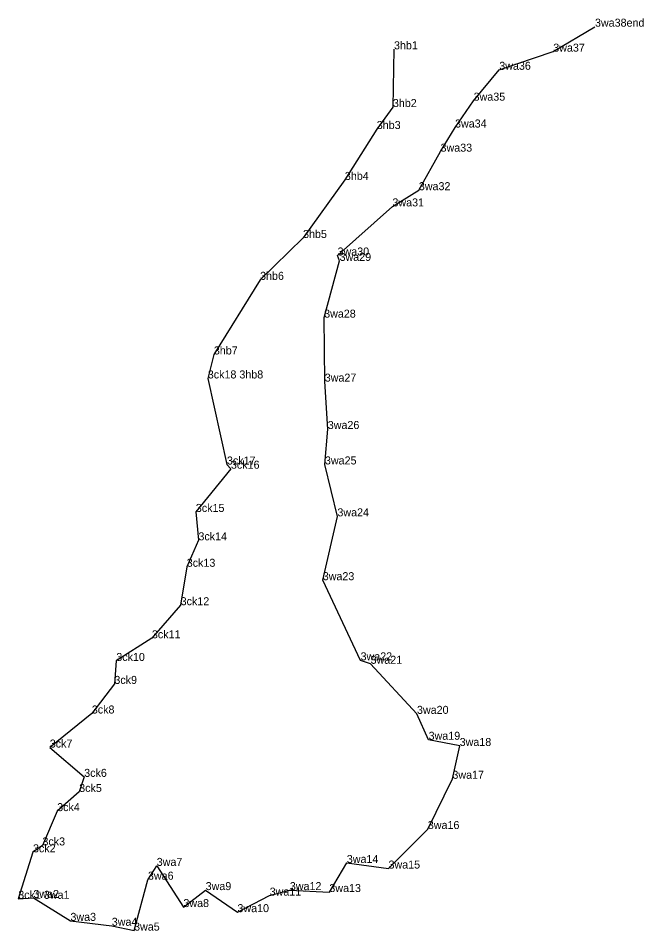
# Model space of a CAD drawing. Extents: x 2072529 to 2267990, y 436423 to 470008.
# Drawn here: x 2089643 to 2090033, y 461992 to 462561 of the extents above; entities that cross this region are included whole.
import ezdxf

# ---------------------------------------------------------------- set-up
doc = ezdxf.new("R2010")
doc.units = 0
doc.layers.add('Level 3', color=7, linetype='Continuous')
doc.layers.add('Old_Level_52', color=7, linetype='Continuous')

msp = doc.modelspace()

# ---------------------------------------------------------------- linework, layer by layer
at = {"layer": 'Level 3'}
for p, q in [((2090002.893, 462556.146), (2090002.893, 462556.146)), ((2089877.453, 462542.01), (2089877.453, 462542.01)), ((2089976.852, 462540.552), (2089976.852, 462540.552)), ((2089943.157, 462529.217), (2089943.157, 462529.217)), ((2089876.765, 462505.958), (2089876.765, 462505.958)), ((2089927.158, 462509.936), (2089927.158, 462509.936)), ((2089866.718, 462492.234), (2089866.718, 462492.234)), ((2089915.55, 462493.182), (2089915.55, 462493.182)), ((2089906.523, 462478.097), (2089906.523, 462478.097)), ((2089846.812, 462460.44), (2089846.812, 462460.44)), ((2089892.973, 462454.032), (2089892.973, 462454.032)), ((2089876.482, 462443.906), (2089876.482, 462443.906)), ((2089820.713, 462424.198), (2089820.713, 462424.198)), ((2089842.248, 462413.247), (2089842.248, 462413.247)), ((2089843.485, 462409.887), (2089843.485, 462409.887)), ((2089793.876, 462398.048), (2089793.876, 462398.048)), ((2089833.871, 462374.449), (2089833.871, 462374.449)), ((2089765.03, 462351.45), (2089765.03, 462351.45)), ((2089761.259, 462336.467), (2089761.259, 462336.467)), ((2089834.231, 462334.49), (2089834.231, 462334.49)), ((2089836.124, 462304.892), (2089836.124, 462304.892)), ((2089834.357, 462282.767), (2089834.357, 462282.767)), ((2089773.188, 462282.704), (2089773.188, 462282.704)), ((2089775.7, 462280.09), (2089775.7, 462280.09)), ((2089753.794, 462253.106), (2089753.794, 462253.106)), ((2089842.135, 462250.349), (2089842.135, 462250.349)), ((2089755.406, 462235.378), (2089755.406, 462235.378)), ((2089748.115, 462218.855), (2089748.115, 462218.855)), ((2089832.988, 462210.469), (2089832.988, 462210.469)), ((2089744.316, 462194.843), (2089744.316, 462194.843)), ((2089726.366, 462174.184), (2089726.366, 462174.184)), ((2089704.14, 462160.043), (2089704.14, 462160.043)), ((2089856.597, 462160.417), (2089856.597, 462160.417)), ((2089862.86, 462158.275), (2089862.86, 462158.275)), ((2089702.953, 462145.705), (2089702.953, 462145.705)), ((2089688.872, 462127.212), (2089688.872, 462127.212)), ((2089891.808, 462127.004), (2089891.808, 462127.004)), ((2089899.057, 462110.822), (2089899.057, 462110.822)), ((2089918.449, 462106.941), (2089918.449, 462106.941)), ((2089662.621, 462105.954), (2089662.621, 462105.954)), ((2089684.116, 462087.643), (2089684.116, 462087.643)), ((2089913.897, 462086.464), (2089913.897, 462086.464)), ((2089680.986, 462078.211), (2089680.986, 462078.211)), ((2089667.237, 462066.265), (2089667.237, 462066.265)), ((2089898.578, 462055.082), (2089898.578, 462055.082)), ((2089658.039, 462044.826), (2089658.039, 462044.826)), ((2089652.149, 462040.552), (2089652.149, 462040.552)), ((2089729.372, 462032.042), (2089729.372, 462032.042)), ((2089848.005, 462033.869), (2089848.005, 462033.869)), ((2089874.035, 462030.376), (2089874.035, 462030.376)), ((2089723.909, 462023.425), (2089723.909, 462023.425)), ((2089759.919, 462016.935), (2089759.919, 462016.935)), ((2089812.451, 462016.937), (2089812.451, 462016.937)), ((2089837.118, 462015.732), (2089837.118, 462015.732)), ((2089642.96, 462011.495), (2089642.96, 462011.495)), ((2089652.392, 462012.03), (2089652.392, 462012.03)), ((2089799.86, 462013.491), (2089799.86, 462013.491)), ((2089746.019, 462006.339), (2089746.019, 462006.339)), ((2089779.746, 462003.159), (2089779.746, 462003.159)), ((2089675.515, 461997.724), (2089675.515, 461997.724)), ((2089701.311, 461994.659), (2089701.311, 461994.659)), ((2089715.244, 461991.622), (2089715.244, 461991.622))]:
    msp.add_line(p, q, dxfattribs=at)
at = {"layer": 'Old_Level_52'}
msp.add_lwpolyline([(2089877.453, 462542.01), (2089876.765, 462505.958), (2089866.718, 462492.234), (2089846.812, 462460.44), (2089820.713, 462424.198), (2089793.876, 462398.048), (2089765.03, 462351.45), (2089761.259, 462336.467), (2089773.188, 462282.704), (2089775.7, 462280.09), (2089753.794, 462253.106), (2089755.406, 462235.378), (2089748.115, 462218.855), (2089744.316, 462194.843), (2089726.366, 462174.184), (2089704.14, 462160.043), (2089702.953, 462145.705), (2089688.872, 462127.212), (2089662.621, 462105.954), (2089684.116, 462087.643), (2089680.986, 462078.211), (2089667.237, 462066.265), (2089658.039, 462044.826), (2089652.149, 462040.552), (2089642.96, 462011.495), (2089652.392, 462012.03), (2089675.515, 461997.724), (2089701.311, 461994.659), (2089715.244, 461991.622), (2089723.909, 462023.425), (2089729.372, 462032.042), (2089746.019, 462006.339), (2089759.919, 462016.935), (2089779.746, 462003.159), (2089799.86, 462013.491), (2089812.451, 462016.937), (2089837.118, 462015.732), (2089848.005, 462033.869), (2089874.035, 462030.376), (2089898.578, 462055.082), (2089913.897, 462086.464), (2089918.449, 462106.941), (2089899.057, 462110.822), (2089891.808, 462127.004), (2089862.86, 462158.275), (2089856.597, 462160.417), (2089832.988, 462210.469), (2089842.135, 462250.349), (2089834.357, 462282.767), (2089836.124, 462304.892), (2089834.231, 462334.49), (2089833.871, 462374.449), (2089843.485, 462409.887), (2089842.248, 462413.247), (2089876.482, 462443.906), (2089892.973, 462454.032), (2089906.523, 462478.097), (2089915.55, 462493.182), (2089927.158, 462509.936), (2089943.157, 462529.217), (2089976.852, 462540.552), (2090002.893, 462556.146)], dxfattribs=at)

# ---------------------------------------------------------------- texts
for s, p in [('3wa38end', (2090002.893, 462556.146)), ('3hb1', (2089877.453, 462542.01)), ('3wa37', (2089976.852, 462540.552)), ('3wa36', (2089943.157, 462529.217)), ('3hb2', (2089876.765, 462505.958)), ('3wa35', (2089927.158, 462509.936)), ('3hb3', (2089866.718, 462492.234)), ('3wa34', (2089915.55, 462493.182)), ('3wa33', (2089906.523, 462478.097)), ('3hb4', (2089846.812, 462460.44)), ('3wa32', (2089892.973, 462454.032)), ('3wa31', (2089876.482, 462443.906)), ('3hb5', (2089820.713, 462424.198)), ('3wa30', (2089842.248, 462413.247)), ('3wa29', (2089843.485, 462409.887)), ('3hb6', (2089793.876, 462398.048)), ('3wa28', (2089833.871, 462374.449)), ('3hb7', (2089765.03, 462351.45)), ('3ck18 3hb8', (2089761.259, 462336.467)), ('3wa27', (2089834.231, 462334.49)), ('3wa26', (2089836.124, 462304.892)), ('3ck17', (2089773.188, 462282.704)), ('3ck16', (2089775.7, 462280.09)), ('3wa25', (2089834.357, 462282.767)), ('3ck15', (2089753.794, 462253.106)), ('3wa24', (2089842.135, 462250.349)), ('3ck14', (2089755.406, 462235.378)), ('3ck13', (2089748.115, 462218.855)), ('3wa23', (2089832.988, 462210.469)), ('3ck12', (2089744.316, 462194.843)), ('3ck11', (2089726.366, 462174.184)), ('3ck10', (2089704.14, 462160.043)), ('3wa22', (2089856.597, 462160.417)), ('3wa21', (2089862.86, 462158.275)), ('3ck9', (2089702.953, 462145.705)), ('3ck8', (2089688.872, 462127.212)), ('3wa20', (2089891.808, 462127.004)), ('3wa19', (2089899.057, 462110.822)), ('3wa18', (2089918.449, 462106.941)), ('3ck7', (2089662.621, 462105.954)), ('3ck6', (2089684.116, 462087.643)), ('3wa17', (2089913.897, 462086.464)), ('3ck5', (2089680.986, 462078.211)), ('3ck4', (2089667.237, 462066.265)), ('3wa16', (2089898.578, 462055.082)), ('3ck3', (2089658.039, 462044.826)), ('3ck2', (2089652.149, 462040.552)), ('3wa14', (2089848.005, 462033.869)), ('3wa7', (2089729.372, 462032.042)), ('3wa15', (2089874.035, 462030.376)), ('3wa6', (2089723.909, 462023.425)), ('3wa9', (2089759.919, 462016.935)), ('3wa12', (2089812.451, 462016.937)), ('3wa13', (2089837.118, 462015.732)), ('3ck1 3wa1', (2089642.96, 462011.495)), ('3wa2', (2089652.392, 462012.03)), ('3wa11', (2089799.86, 462013.491)), ('3wa8', (2089746.019, 462006.339)), ('3wa10', (2089779.746, 462003.159)), ('3wa3', (2089675.515, 461997.724)), ('3wa4', (2089701.311, 461994.659)), ('3wa5', (2089715.244, 461991.622))]:
    msp.add_text(s, height=5).set_placement(p)

doc.saveas('drawing.dxf')
